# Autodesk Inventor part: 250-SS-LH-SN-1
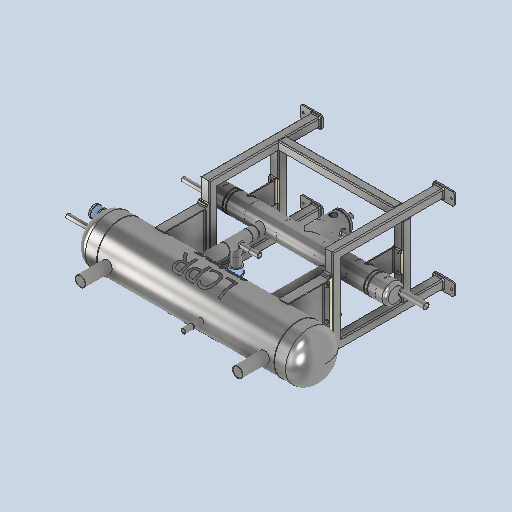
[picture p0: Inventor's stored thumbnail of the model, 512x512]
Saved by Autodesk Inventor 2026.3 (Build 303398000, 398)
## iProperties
Created: 2026-05
Part Number: 250-SS-LH-SN-1
Material: Generic
Document SubType Name: Modeling
Designer: rva
Density: 1 g/cm^3
Appearance: Default
Author: rva
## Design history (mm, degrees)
derived "250-SS-LH-SN.iam"
body "Solid1"
node "LCPR-SS-100- Sub Cooler.iam:1::ISO 5251 Equal Tee DN100 3.6 "
node "LCPR-SS-100- Sub Cooler.iam:1::ISO 5251 Reducing Tee DN100 x"
node "LCPR-SS-100- Sub Cooler.iam:1::ISO 5251 Reducing Tee DN100 x"
node "LCPR-SS-100- Sub Cooler.iam:1::SS-100-14 hole Sub Cooler Pla"
node "LCPR-SS-100- Sub Cooler.iam:1::SS-100-14 hole Sub Cooler Pla"
node "LCPR-SS-100- Sub Cooler.iam:1::100 mm Subcooler Leg.ipt:1"
node "LCPR-SS-100- Sub Cooler.iam:1::LCPR-SS-100 Blank Plate.ipt:1"
node "LCPR-SS-100- Sub Cooler.iam:1::100 mm Subcooler Leg.ipt:2"
node "LCPR-SS-100- Sub Cooler.iam:1::1-2 Inch NPT Socket - SS.ipt:"
node "LCPR-SS-100- Sub Cooler.iam:1::H1100-R.ipt:1"
node "LCPR-SS-100- Sub Cooler.iam:1::H1100-R.ipt:2"
node "LCPR-SS-100- Sub Cooler.iam:1::1-2 Inch NPT Socket - SS.ipt:"
node "LCPR-SS-100- Sub Cooler.iam:1::1-2 Inch NPT Socket - SS.ipt:"
node "LCPR-SS-100- Sub Cooler.iam:1::Welds"
node "LCPR-SS-250-Frame Assembly.iam:2::LCPR-SS-250-120 x 70 Frame"
node "LCPR-SS-250-Frame Assembly.iam:2::LCPR-SS-250-120 x 70 Frame"
node "LCPR-SS-250-Frame Assembly.iam:2::LCPR-SS-250-120 x 70 Frame"
node "LCPR-SS-250-Frame Assembly.iam:2::LCPR-SS-250-120 x 70 Frame"
node "LCPR-SS-250-Frame Assembly.iam:2::Welds"
node "Nylon Heat Tranfer Spacer 276.5x50.ipt:1"
node "Nylon Heat Tranfer Spacer 276.5x50.ipt:2"
node "AS 1111 - Metric M10 x 80:1"
node "AS 1112 (4) - Metric M10:1"
node "AS 1237 (4.1) 10 mm:1"
node "AS 1237 (4.1) 10 mm:2"
node "AS 1111 - Metric M10 x 80:2"
node "AS 1112 (4) - Metric M10:2"
node "AS 1237 (4.1) 10 mm:3"
node "AS 1237 (4.1) 10 mm:4"
node "AS 1111 - Metric M10 x 80:3"
node "AS 1112 (4) - Metric M10:3"
node "AS 1237 (4.1) 10 mm:5"
node "AS 1237 (4.1) 10 mm:6"
node "AS 1111 - Metric M10 x 80:4"
node "AS 1112 (4) - Metric M10:4"
node "AS 1237 (4.1) 10 mm:7"
node "AS 1237 (4.1) 10 mm:8"
node "250-SS-SHELL-SN-WELD.iam:1::ASME B36.10M Pipe 10.75 x 0.165 "
node "250-SS-SHELL-SN-WELD.iam:1::LCPR-LOGO.ipt:1"
node "250-SS-SHELL-SN-WELD.iam:1::LCPR-SS-250 mm Dome End Cap.ipt:"
node "250-SS-SHELL-SN-WELD.iam:1::H1100-R.ipt:1"
node "250-SS-SHELL-SN-WELD.iam:1::LCPR-SS-250-Leg Assembly.iam:1::"
node "250-SS-SHELL-SN-WELD.iam:1::LCPR-SS-250-Leg Assembly.iam:2::"
node "250-SS-SHELL-SN-WELD.iam:1::LCPR-SS-250 mm Dome End Cap.ipt:"
node "Nylon Heat Tranfer Spacer 120x50.ipt:1"
node "Nylon Heat Tranfer Spacer 120x50.ipt:2"
node "250-SS-LH-SN.iam_Bodies"
